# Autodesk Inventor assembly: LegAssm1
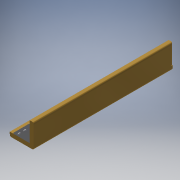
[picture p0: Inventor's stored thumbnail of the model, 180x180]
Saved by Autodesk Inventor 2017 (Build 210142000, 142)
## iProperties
Created: 2017-05
Part Number: LegAssm1
Document SubType Name: Assembly
Designer: Savy
Author: Savy
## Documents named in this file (5)
- D:\Users\Savy\Documents\Infinity Table\LegAssm1.iam
- D:\Users\Savy\Documents\Infinity Table\Leg1.ipt
- D:\Users\Savy\Documents\Infinity Table\Leg2.ipt
- D:\Users\Savy\Documents\Infinity Table\CornerShelfBracket.ipt
- D:\Users\Savy\Documents\Infinity Table\8_Screw_-5inch.ipt
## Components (16 placed, 16 different names)
1. Leg1_1001
2. Leg2_1002 — Flush:1
3. CornerShelfBracket_1003
4. CornerShelfBracket_1004 — Flush:1, Mate:1, Mate:2, Mate:3, Mate:4, Mate:5, Mate:6
5. 8_Screw_-5inch_1005
6. 8_Screw_-5inch_1006
7. 8_Screw_-5inch_1007 — Mate:5
8. 8_Screw_-5inch_1008 — Mate:6
9. 8_Screw_-5inch_1009 — Mate:4
10. 8_Screw_-5inch_1010 — Mate:3
11. 8_Screw_-5inch_1011
12. 8_Screw_-5inch_1012
13. 8_Screw_-5inch_1013
14. 8_Screw_-5inch_1014
15. 8_Screw_-5inch_1015 — Mate:1
16. 8_Screw_-5inch_1016 — Mate:2
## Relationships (7: Mate 6, Flush 1)
- Flush:1: Leg2_1002 ↔ CornerShelfBracket_1004
- Mate:1: CornerShelfBracket_1004 ↔ 8_Screw_-5inch_1015
- Mate:2: CornerShelfBracket_1004 ↔ 8_Screw_-5inch_1016
- Mate:3: CornerShelfBracket_1004 ↔ 8_Screw_-5inch_1010
- Mate:4: CornerShelfBracket_1004 ↔ 8_Screw_-5inch_1009
- Mate:5: CornerShelfBracket_1004 ↔ 8_Screw_-5inch_1007
- Mate:6: CornerShelfBracket_1004 ↔ 8_Screw_-5inch_1008
